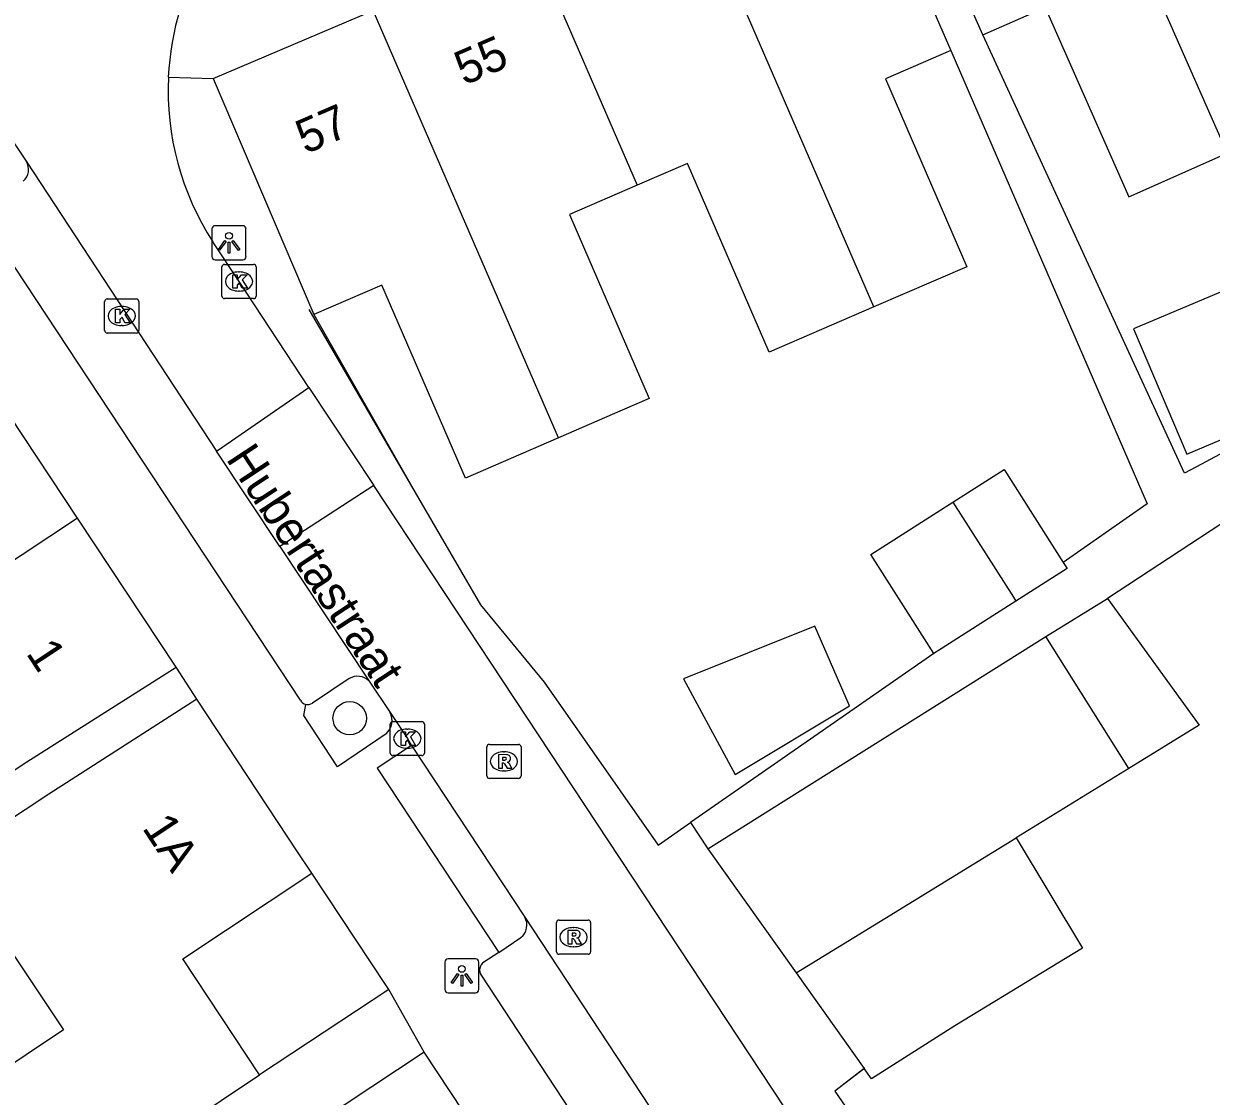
# Model space of a CAD drawing. Extents: x 159718 to 160783, y 383290 to 384030.
# Drawn here: x 160315.43 to 160350.21, y 383461.22 to 383492.63 of the extents above; entities that cross this region are included whole.
import ezdxf

# ---------------------------------------------------------------- set-up
doc = ezdxf.new("R2010")
doc.units = 0
for name, color, linetype in [('IMGEO_Boom', 7, 'Continuous'), ('IMGEO_Erf', 7, 'Continuous'), ('IMGEO_Kolk', 7, 'Continuous'), ('IMGEO_Lichtpunt', 7, 'Continuous'), ('IMGEO_Muur', 7, 'Continuous'), ('IMGEO_Openbare_ruimte_label', 7, 'Continuous'), ('IMGEO_Pand', 7, 'Continuous'), ('IMGEO_Pand_nummerreeks', 7, 'Continuous'), ('IMGEO_Parkeervlak_open', 7, 'Continuous'), ('IMGEO_Rijbaan_lokaal_open', 7, 'Continuous'), ('IMGEO_Rioolput', 7, 'Continuous'), ('IMGEO_Voetpad_open', 7, 'Continuous')]:
    doc.layers.add(name, color=color, linetype=linetype)

msp = doc.modelspace()

# ---------------------------------------------------------------- linework, layer by layer
at = {"layer": 'IMGEO_Boom'}
msp.add_circle((160324.974, 383472.289), 0.489, dxfattribs=at)
at = {"layer": 'IMGEO_Erf'}
msp.add_lwpolyline([(160326.123, 383464.339), (160322.334, 383461.84)], dxfattribs=at)
at = {"layer": 'IMGEO_Kolk'}
for p, q in [((160321.233, 383484.657), (160321.233, 383485.509)), ((160321.308, 383485.583), (160322.16, 383485.583)), ((160321.721, 383485.363), (160321.746, 383485.363)), ((160322.234, 383485.509), (160322.234, 383484.657)), ((160317.873, 383484.572), (160318.725, 383484.572)), ((160322.16, 383484.583), (160321.308, 383484.583)), ((160321.744, 383484.803), (160321.719, 383484.803)), ((160317.798, 383483.646), (160317.798, 383484.498)), ((160318.286, 383484.352), (160318.311, 383484.352)), ((160318.799, 383484.498), (160318.799, 383483.646)), ((160318.725, 383483.572), (160317.873, 383483.572)), ((160318.309, 383483.792), (160318.284, 383483.792)), ((160326.161, 383471.267), (160326.161, 383472.119)), ((160326.236, 383472.193), (160327.088, 383472.193)), ((160327.162, 383472.119), (160327.162, 383471.267)), ((160326.649, 383471.973), (160326.674, 383471.973)), ((160326.672, 383471.413), (160326.647, 383471.413)), ((160327.088, 383471.193), (160326.236, 383471.193))]:
    msp.add_line(p, q, dxfattribs=at)
for points in [[(160321.233, 383484.657), (160321.233, 383485.509)], [(160321.308, 383485.583), (160322.16, 383485.583)], [(160321.554, 383485.283), (160321.677, 383485.283), (160321.677, 383485.132), (160321.807, 383485.283), (160321.971, 383485.283), (160321.825, 383485.132), (160321.978, 383484.883), (160321.826, 383484.883), (160321.741, 383485.047), (160321.677, 383484.98), (160321.677, 383484.883), (160321.554, 383484.883), (160321.554, 383485.283)], [(160322.234, 383485.509), (160322.234, 383484.657)], [(160317.873, 383484.572), (160318.725, 383484.572)], [(160322.16, 383484.583), (160321.308, 383484.583)], [(160317.798, 383483.646), (160317.798, 383484.498)], [(160318.119, 383484.272), (160318.242, 383484.272), (160318.242, 383484.121), (160318.372, 383484.272), (160318.536, 383484.272), (160318.39, 383484.121), (160318.543, 383483.872), (160318.391, 383483.872), (160318.306, 383484.036), (160318.242, 383483.969), (160318.242, 383483.872), (160318.119, 383483.872), (160318.119, 383484.272)], [(160318.799, 383484.498), (160318.799, 383483.646)], [(160318.725, 383483.572), (160317.873, 383483.572)], [(160326.161, 383471.267), (160326.161, 383472.119)], [(160326.236, 383472.193), (160327.088, 383472.193)], [(160327.162, 383472.119), (160327.162, 383471.267)], [(160326.482, 383471.893), (160326.605, 383471.893), (160326.605, 383471.742), (160326.735, 383471.893), (160326.899, 383471.893), (160326.753, 383471.742), (160326.906, 383471.493), (160326.754, 383471.493), (160326.669, 383471.657), (160326.605, 383471.59), (160326.605, 383471.493), (160326.482, 383471.493), (160326.482, 383471.893)], [(160327.088, 383471.193), (160326.236, 383471.193)]]:
    msp.add_lwpolyline(points, dxfattribs=at)
for centre, start, end in [((160321.31, 383485.507), 91.552, 178.448), ((160321.31, 383485.507), 91.552, 178.448), ((160322.158, 383485.507), 1.552, 88.448), ((160322.158, 383485.507), 1.552, 88.448), ((160317.875, 383484.496), 91.552, 178.448), ((160317.875, 383484.496), 91.552, 178.448), ((160318.723, 383484.496), 1.552, 88.448), ((160318.723, 383484.496), 1.552, 88.448), ((160321.31, 383484.659), 181.552, 268.448), ((160321.31, 383484.659), 181.552, 268.448), ((160322.158, 383484.659), 271.552, 358.448), ((160322.158, 383484.659), 271.552, 358.448), ((160317.875, 383483.648), 181.552, 268.448), ((160317.875, 383483.648), 181.552, 268.448), ((160318.723, 383483.648), 271.552, 358.448), ((160318.723, 383483.648), 271.552, 358.448), ((160326.238, 383472.117), 91.552, 178.448), ((160326.238, 383472.117), 91.552, 178.448), ((160327.086, 383472.117), 1.552, 88.448), ((160327.086, 383472.117), 1.552, 88.448), ((160326.238, 383471.269), 181.552, 268.448), ((160326.238, 383471.269), 181.552, 268.448), ((160327.086, 383471.269), 271.552, 358.448), ((160327.086, 383471.269), 271.552, 358.448)]:
    msp.add_arc(centre, 0.0765, start, end, dxfattribs=at)
for centre, major_axis, ratio, start_param, end_param in [((160321.72, 383485.083), (-0.387, 0.002), 0.722429, 4.712389, 7.853982), ((160321.745, 383485.083), (-0.39, 0.002), 0.717154, 1.570796, 4.712389), ((160318.285, 383484.072), (-0.387, 0.002), 0.722429, 4.712389, 7.853982), ((160318.31, 383484.072), (-0.39, 0.002), 0.717154, 1.570796, 4.712389), ((160326.648, 383471.693), (-0.387, 0.002), 0.722429, 4.712389, 7.853982), ((160326.673, 383471.693), (-0.39, 0.002), 0.717154, 1.570796, 4.712389)]:
    msp.add_ellipse(centre, major_axis=major_axis, ratio=ratio, start_param=start_param, end_param=end_param, dxfattribs=at)
at = {"layer": 'IMGEO_Lichtpunt'}
for p, q in [((160321.843, 383486.717), (160321.035, 383486.717)), ((160321.843, 383486.717), (160321.035, 383486.717)), ((160320.941, 383486.622), (160320.941, 383485.815)), ((160320.941, 383486.622), (160320.941, 383485.815)), ((160321.937, 383485.815), (160321.937, 383486.622)), ((160321.937, 383485.815), (160321.937, 383486.622)), ((160321.035, 383485.721), (160321.843, 383485.721)), ((160321.035, 383485.721), (160321.843, 383485.721)), ((160327.76, 383465.148), (160327.76, 383464.341)), ((160327.76, 383465.148), (160327.76, 383464.341)), ((160328.662, 383465.243), (160327.854, 383465.243)), ((160328.662, 383465.243), (160327.854, 383465.243)), ((160328.756, 383464.341), (160328.756, 383465.148)), ((160328.756, 383464.341), (160328.756, 383465.148)), ((160327.854, 383464.247), (160328.662, 383464.247)), ((160327.854, 383464.247), (160328.662, 383464.247))]:
    msp.add_line(p, q, dxfattribs=at)
for points in [[(160321.315, 383486.286), (160321.354, 383486.258), (160321.166, 383485.996), (160321.128, 383486.023), (160321.315, 383486.286)], [(160321.417, 383486.238), (160321.464, 383486.238), (160321.464, 383485.916), (160321.417, 383485.916), (160321.417, 383486.238)], [(160321.527, 383486.258), (160321.565, 383486.285), (160321.752, 383486.023), (160321.713, 383485.995), (160321.527, 383486.258)], [(160328.134, 383464.812), (160328.173, 383464.784), (160327.985, 383464.522), (160327.947, 383464.549), (160328.134, 383464.812)], [(160328.236, 383464.764), (160328.283, 383464.764), (160328.283, 383464.442), (160328.236, 383464.442), (160328.236, 383464.764)], [(160328.346, 383464.784), (160328.384, 383464.811), (160328.571, 383464.549), (160328.532, 383464.521), (160328.346, 383464.784)]]:
    msp.add_lwpolyline(points, dxfattribs=at)
for centre in [(160321.44, 383486.42), (160328.259, 383464.946)]:
    msp.add_circle(centre, 0.0994, dxfattribs=at)
for centre, start, end in [((160321.035, 383486.622), 90, 180), ((160321.035, 383486.622), 90, 180), ((160321.843, 383486.622), 0, 90), ((160321.843, 383486.622), 0, 90), ((160321.035, 383485.815), 180, 270), ((160321.035, 383485.815), 180, 270), ((160321.843, 383485.815), 270, 0), ((160321.843, 383485.815), 270, 360), ((160327.854, 383465.148), 90, 180), ((160327.854, 383465.148), 90, 180), ((160328.662, 383465.148), 0, 90), ((160328.662, 383465.148), 0, 90), ((160327.854, 383464.341), 180, 270), ((160327.854, 383464.341), 180, 270), ((160328.662, 383464.341), 270, 0), ((160328.662, 383464.341), 270, 360)]:
    msp.add_arc(centre, 0.0946, start, end, dxfattribs=at)
at = {"layer": 'IMGEO_Muur'}
for points in [[(160323.781, 383484.267), (160327.07, 383478.603)], [(160340.059, 383462.041), (160339.18, 383461.368), (160346.797, 383450.296)]]:
    msp.add_lwpolyline(points, dxfattribs=at)
at = {"layer": 'IMGEO_Pand'}
for points in [[(160345.126, 383501.421), (160345.752, 383500), (160350.674, 383488.838)], [(160343.517, 383492.308), (160342.327, 383495.007), (160340.568, 383499.373)], [(160339.658, 383498.966), (160341.388, 383494.596), (160342.579, 383491.845)], [(160340.32, 383484.337), (160334.864, 383496.934)], [(160330.319, 383495.003), (160333.393, 383487.904)], [(160320.978, 383491.032), (160325.666, 383493.025)], [(160331.087, 383480.503), (160325.666, 383493.025)], [(160343.517, 383492.308), (160345.344, 383493.113), (160347.79, 383487.566), (160350.674, 383488.838)], [(160342.579, 383491.845), (160340.662, 383491.015), (160343.043, 383485.516), (160340.32, 383484.337)], [(160320.978, 383491.032), (160323.925, 383484.119)], [(160340.32, 383484.337), (160337.259, 383483.012), (160334.865, 383488.541), (160333.393, 383487.904)], [(160333.393, 383487.904), (160331.413, 383487.047), (160333.748, 383481.655), (160332.951, 383481.31), (160331.087, 383480.503)], [(160331.087, 383480.503), (160328.362, 383479.323), (160325.914, 383484.979), (160323.925, 383484.119)], [(160352.286, 383481.211), (160350.728, 383484.882), (160347.928, 383483.693), (160349.486, 383480.023), (160352.286, 383481.211)], [(160317.002, 383478.148), (160314.234, 383482.33)], [(160342.639, 383478.622), (160344.139, 383479.577), (160345.872, 383476.854)], [(160342.078, 383474.19), (160340.232, 383477.09), (160342.639, 383478.622)], [(160342.639, 383478.622), (160344.413, 383475.836), (160344.485, 383475.723)], [(160317.002, 383478.148), (160310.482, 383473.836)], [(160319.888, 383473.788), (160317.002, 383478.148)], [(160345.872, 383476.854), (160345.985, 383476.677), (160344.485, 383475.723)], [(160344.485, 383475.723), (160342.078, 383474.19)], [(160345.36, 383474.681), (160347.169, 383475.795)], [(160347.169, 383475.795), (160349.856, 383472.083), (160347.792, 383470.815)], [(160339.607, 383472.649), (160338.593, 383474.99), (160334.749, 383473.441), (160336.259, 383470.644), (160339.607, 383472.649)], [(160335.459, 383468.466), (160345.36, 383474.681)], [(160347.792, 383470.815), (160345.36, 383474.681)], [(160310.482, 383473.836), (160311.553, 383472.215), (160306.482, 383468.864), (160308.24, 383466.203), (160315.517, 383471.013), (160319.888, 383473.788)], [(160320.501, 383472.85), (160316.163, 383470.065), (160308.387, 383464.917), (160310.11, 383462.341), (160314.972, 383465.593), (160316.595, 383463.166), (160314.392, 383461.692), (160316.781, 383458.12), (160322.334, 383461.84)], [(160323.863, 383467.752), (160323.45, 383468.378), (160320.501, 383472.85)], [(160347.792, 383470.815), (160344.494, 383468.789)], [(160338.052, 383464.827), (160340.646, 383466.423), (160344.494, 383468.789)], [(160344.494, 383468.789), (160346.437, 383465.549), (160342.694, 383463.274), (160340.259, 383461.73), (160340.045, 383462.03)], [(160335.459, 383468.466), (160338.052, 383464.827)], [(160322.334, 383461.84), (160320.084, 383465.243), (160323.863, 383467.752)], [(160338.052, 383464.827), (160340.045, 383462.03)], [(160327.156, 383462.508), (160320.906, 383458.365), (160325.09, 383452.053)], [(160331.323, 383456.203), (160327.156, 383462.508)]]:
    msp.add_lwpolyline(points, dxfattribs=at)
at = {"layer": 'IMGEO_Parkeervlak_open'}
msp.add_lwpolyline([(160324.961, 383473.449), (160323.88, 383472.731)], dxfattribs=at)
for centre, radius, start, end in [((160315.11, 383488.363), 0.459, 311.8313, 31.5503), ((160325.205, 383473.046), 0.472, 44.8031, 121.2149), ((160323.744, 383472.922), 0.234, 257.4672, 305.5059)]:
    msp.add_arc(centre, radius, start, end, dxfattribs=at)
at = {"layer": 'IMGEO_Rijbaan_lokaal_open'}
for points in [[(160314.883, 383489.53), (160315.501, 383488.603)], [(160315.501, 383488.603), (160321.07, 383480.112)], [(160323.782, 383481.981), (160321.734, 383485.083), (160320.97, 383486.241)], [(160321.07, 383480.112), (160323.782, 383481.981)], [(160323.782, 383481.981), (160325.677, 383479.111)], [(160322.931, 383477.317), (160321.07, 383480.112)], [(160325.677, 383479.111), (160322.931, 383477.317)], [(160348.927, 383443.894), (160348.384, 383444.716), (160325.677, 383479.111)], [(160322.931, 383477.317), (160325.54, 383473.378)], [(160325.54, 383473.378), (160326.155, 383472.455)], [(160326.155, 383472.455), (160326.662, 383471.693), (160326.787, 383471.49)], [(160326.787, 383471.49), (160330.101, 383466.464)], [(160330.101, 383466.464), (160337.159, 383455.728)]]:
    msp.add_lwpolyline(points, dxfattribs=at)
for centre, radius, start, end in [((160327.829, 383490.692), 8.175, 120.8352, 177.3693), ((160327.822, 383490.687), 8.167, 177.3301, 212.9771)]:
    msp.add_arc(centre, radius, start, end, dxfattribs=at)
at = {"layer": 'IMGEO_Rioolput'}
for p, q in [((160328.991, 383470.598), (160328.991, 383471.45)), ((160329.066, 383471.524), (160329.918, 383471.524)), ((160329.992, 383471.45), (160329.992, 383470.598)), ((160329.479, 383471.304), (160329.504, 383471.304)), ((160329.502, 383470.744), (160329.477, 383470.744)), ((160329.918, 383470.524), (160329.066, 383470.524)), ((160331.029, 383465.45), (160331.029, 383466.302)), ((160331.104, 383466.376), (160331.956, 383466.376)), ((160331.517, 383466.156), (160331.542, 383466.156)), ((160332.03, 383466.302), (160332.03, 383465.45)), ((160331.54, 383465.596), (160331.515, 383465.596)), ((160331.956, 383465.376), (160331.104, 383465.376))]:
    msp.add_line(p, q, dxfattribs=at)
for points in [[(160328.991, 383470.598), (160328.991, 383471.45)], [(160329.066, 383471.524), (160329.918, 383471.524)], [(160329.992, 383471.45), (160329.992, 383470.598)], [(160329.58, 383471.222), (160329.328, 383471.224), (160329.328, 383470.824)], [(160329.506, 383471.143), (160329.452, 383471.143), (160329.452, 383471.062)], [(160329.452, 383471.062), (160329.504, 383471.062)], [(160329.328, 383470.824), (160329.452, 383470.824), (160329.452, 383470.986), (160329.463, 383470.986)], [(160329.51, 383470.957), (160329.581, 383470.824), (160329.721, 383470.824), (160329.656, 383470.95)], [(160329.918, 383470.524), (160329.066, 383470.524)], [(160331.029, 383465.45), (160331.029, 383466.302)], [(160331.104, 383466.376), (160331.956, 383466.376)], [(160332.03, 383466.302), (160332.03, 383465.45)], [(160331.618, 383466.074), (160331.366, 383466.076), (160331.366, 383465.676)], [(160331.366, 383465.676), (160331.49, 383465.676), (160331.49, 383465.838), (160331.501, 383465.838)], [(160331.544, 383465.995), (160331.49, 383465.995), (160331.49, 383465.914)], [(160331.49, 383465.914), (160331.542, 383465.914)], [(160331.548, 383465.809), (160331.619, 383465.676), (160331.759, 383465.676), (160331.694, 383465.802)], [(160331.956, 383465.376), (160331.104, 383465.376)]]:
    msp.add_lwpolyline(points, dxfattribs=at)
for centre, radius, start, end in [((160329.068, 383471.448), 0.0765, 91.552, 178.448), ((160329.068, 383471.448), 0.0765, 91.552, 178.448), ((160329.916, 383471.448), 0.0765, 1.552, 88.448), ((160329.916, 383471.448), 0.0765, 1.552, 88.448), ((160329.488, 383471.251), 0.19, 274.7715, 282.9687), ((160329.512, 383471.047), 0.0964, 77.0061, 93.1865), ((160329.526, 383471.104), 0.0378, 276.6634, 79.6772), ((160329.579, 383471.112), 0.109, 350.3612, 89.416), ((160329.577, 383471.112), 0.112, 277.5842, 350.9817), ((160329.561, 383470.897), 0.108, 29.5134, 73.7905), ((160329.462, 383470.933), 0.0533, 26.0293, 88.6989), ((160329.068, 383470.6), 0.0765, 181.552, 268.448), ((160329.068, 383470.6), 0.0765, 181.552, 268.448), ((160329.916, 383470.6), 0.0765, 271.552, 358.448), ((160329.916, 383470.6), 0.0765, 271.552, 358.448), ((160331.106, 383466.3), 0.0765, 91.552, 178.448), ((160331.106, 383466.3), 0.0765, 91.552, 178.448), ((160331.954, 383466.3), 0.0765, 1.552, 88.448), ((160331.954, 383466.3), 0.0765, 1.552, 88.448), ((160331.5, 383465.785), 0.0533, 26.0293, 88.6989), ((160331.526, 383466.103), 0.19, 274.7715, 282.9687), ((160331.55, 383465.899), 0.0964, 77.0061, 93.1865), ((160331.564, 383465.956), 0.0378, 276.6634, 79.6772), ((160331.617, 383465.964), 0.109, 350.3612, 89.416), ((160331.615, 383465.964), 0.112, 277.5842, 350.9817), ((160331.599, 383465.749), 0.108, 29.5134, 73.7905), ((160331.106, 383465.452), 0.0765, 181.552, 268.448), ((160331.106, 383465.452), 0.0765, 181.552, 268.448), ((160331.954, 383465.452), 0.0765, 271.552, 358.448), ((160331.954, 383465.452), 0.0765, 271.552, 358.448)]:
    msp.add_arc(centre, radius, start, end, dxfattribs=at)
for centre, major_axis, ratio, start_param, end_param in [((160329.478, 383471.024), (-0.387, 0.002), 0.722429, 4.712389, 7.853982), ((160329.503, 383471.024), (-0.39, 0.002), 0.717154, 1.570796, 4.712389), ((160331.516, 383465.876), (-0.387, 0.002), 0.722429, 4.712389, 7.853982), ((160331.541, 383465.876), (-0.39, 0.002), 0.717154, 1.570796, 4.712389)]:
    msp.add_ellipse(centre, major_axis=major_axis, ratio=ratio, start_param=start_param, end_param=end_param, dxfattribs=at)
at = {"layer": 'IMGEO_Voetpad_open'}
for points in [[(160377.174, 383495.494), (160347.169, 383475.795)], [(160354.477, 383482.181), (160349.919, 383479.732), (160349.426, 383479.467), (160343.517, 383492.308)], [(160342.579, 383491.845), (160348.328, 383478.567), (160345.872, 383476.854)], [(160319.663, 383491.067), (160320.978, 383491.032)], [(160323.531, 383472.82), (160314.226, 383486.906)], [(160323.925, 383484.119), (160327.07, 383478.603), (160328.805, 383475.616), (160330.671, 383473.35), (160334.004, 383468.573), (160334.955, 383469.237)], [(160342.078, 383474.19), (160334.955, 383469.237)], [(160320.501, 383472.85), (160319.888, 383473.788)], [(160326.038, 383471.836), (160324.618, 383470.866), (160323.629, 383472.374), (160323.693, 383472.693)], [(160326.787, 383471.49), (160325.775, 383470.828), (160329.34, 383465.431)], [(160334.955, 383469.237), (160335.459, 383468.466)], [(160326.123, 383464.339), (160326.025, 383464.488), (160323.863, 383467.752)], [(160329.34, 383465.431), (160329.988, 383465.863)], [(160329.34, 383465.431), (160328.905, 383465.147)], [(160328.82, 383464.762), (160335.102, 383455.207)], [(160327.156, 383462.508), (160326.123, 383464.339)], [(160340.045, 383462.03), (160339.18, 383461.368), (160346.797, 383450.296)]]:
    msp.add_lwpolyline(points, dxfattribs=at)
for centre, radius, start, end in [((160323.736, 383472.915), 0.226, 204.8062, 259.0044), ((160325.718, 383472.217), 0.497, 309.989, 28.6041), ((160329.695, 383466.229), 0.469, 308.6775, 30.0256), ((160329.062, 383464.91), 0.284, 123.5463, 211.5537)]:
    msp.add_arc(centre, radius, start, end, dxfattribs=at)

# ---------------------------------------------------------------- texts
at = {"layer": 'IMGEO_Openbare_ruimte_label'}
msp.add_text('Hubertastraat', height=1, rotation=303.3722, dxfattribs=at).set_placement((160321.331, 383479.89))
at = {"layer": 'IMGEO_Pand_nummerreeks'}
for s, rotation, p in [('55', 23.4053, (160328.326, 383490.815)), ('57', 23.4053, (160323.677, 383488.803)), ('1', 303.472, (160315.476, 383474.194)), ('1A', 303.4663, (160318.877, 383469.076))]:
    msp.add_text(s, height=1, rotation=rotation, dxfattribs=at).set_placement(p)

doc.saveas('drawing.dxf')
